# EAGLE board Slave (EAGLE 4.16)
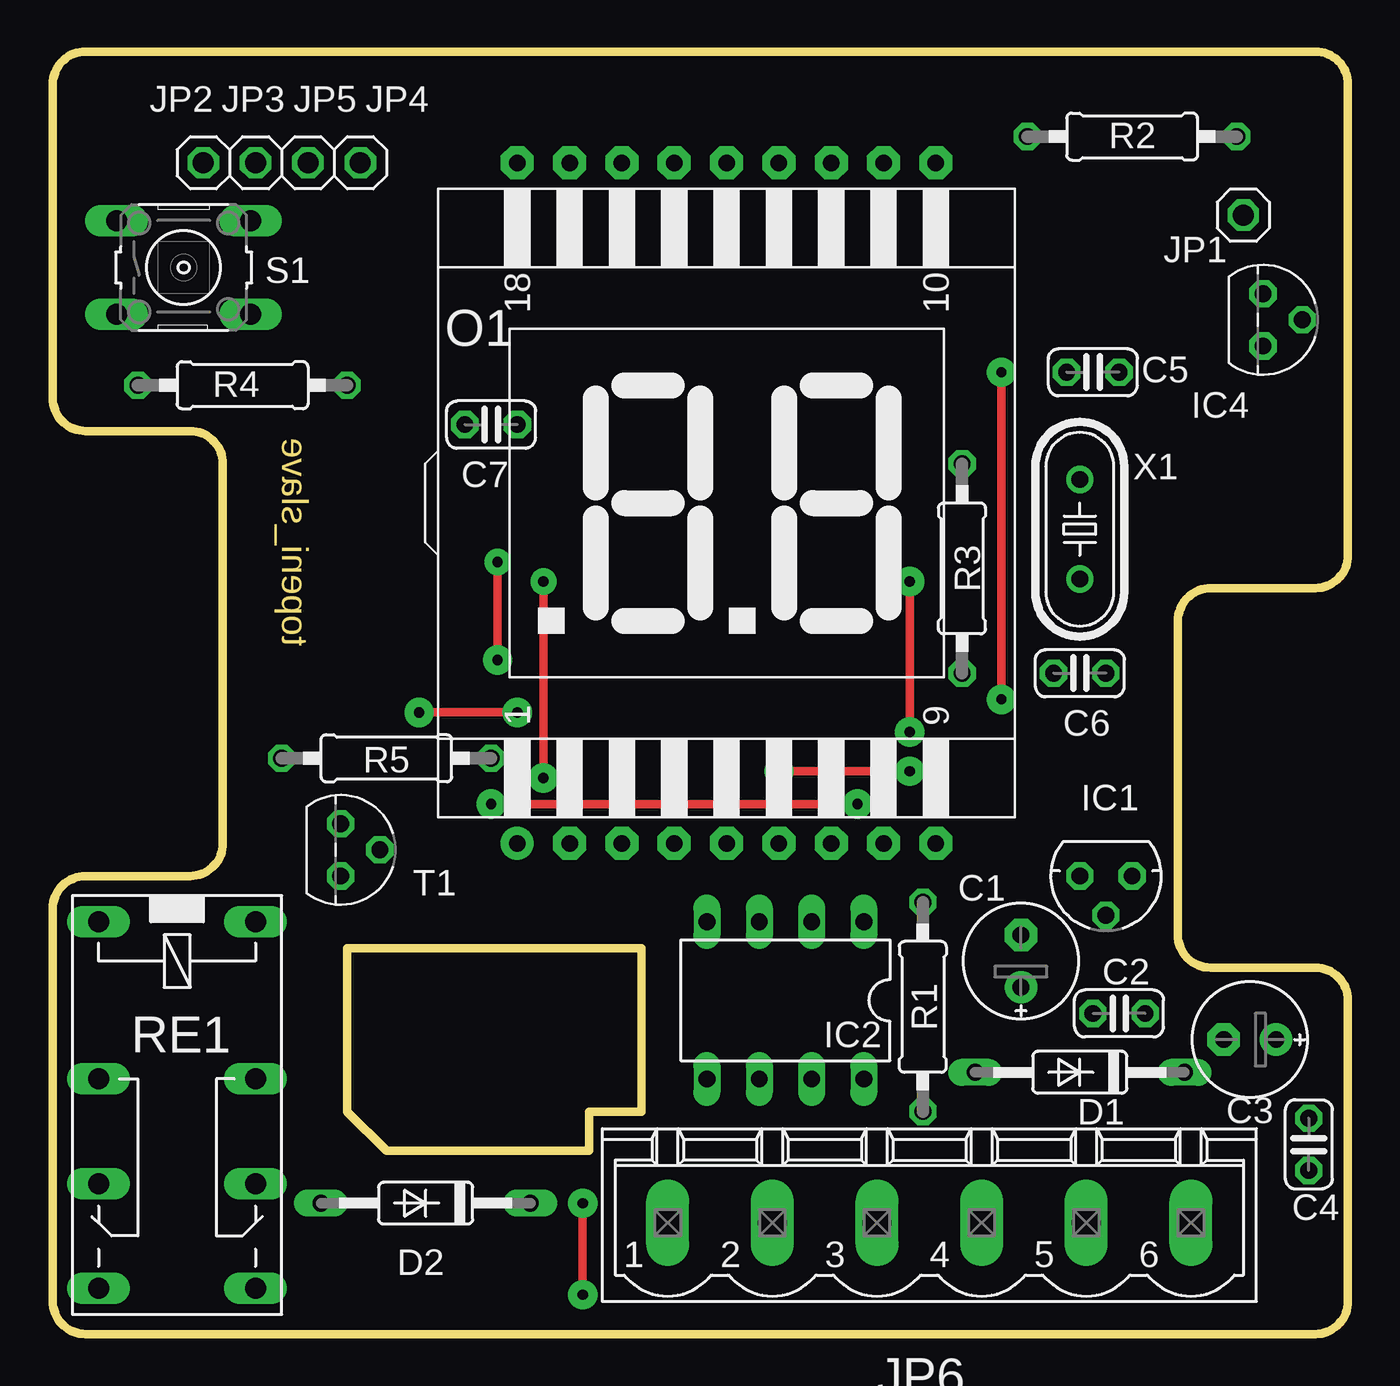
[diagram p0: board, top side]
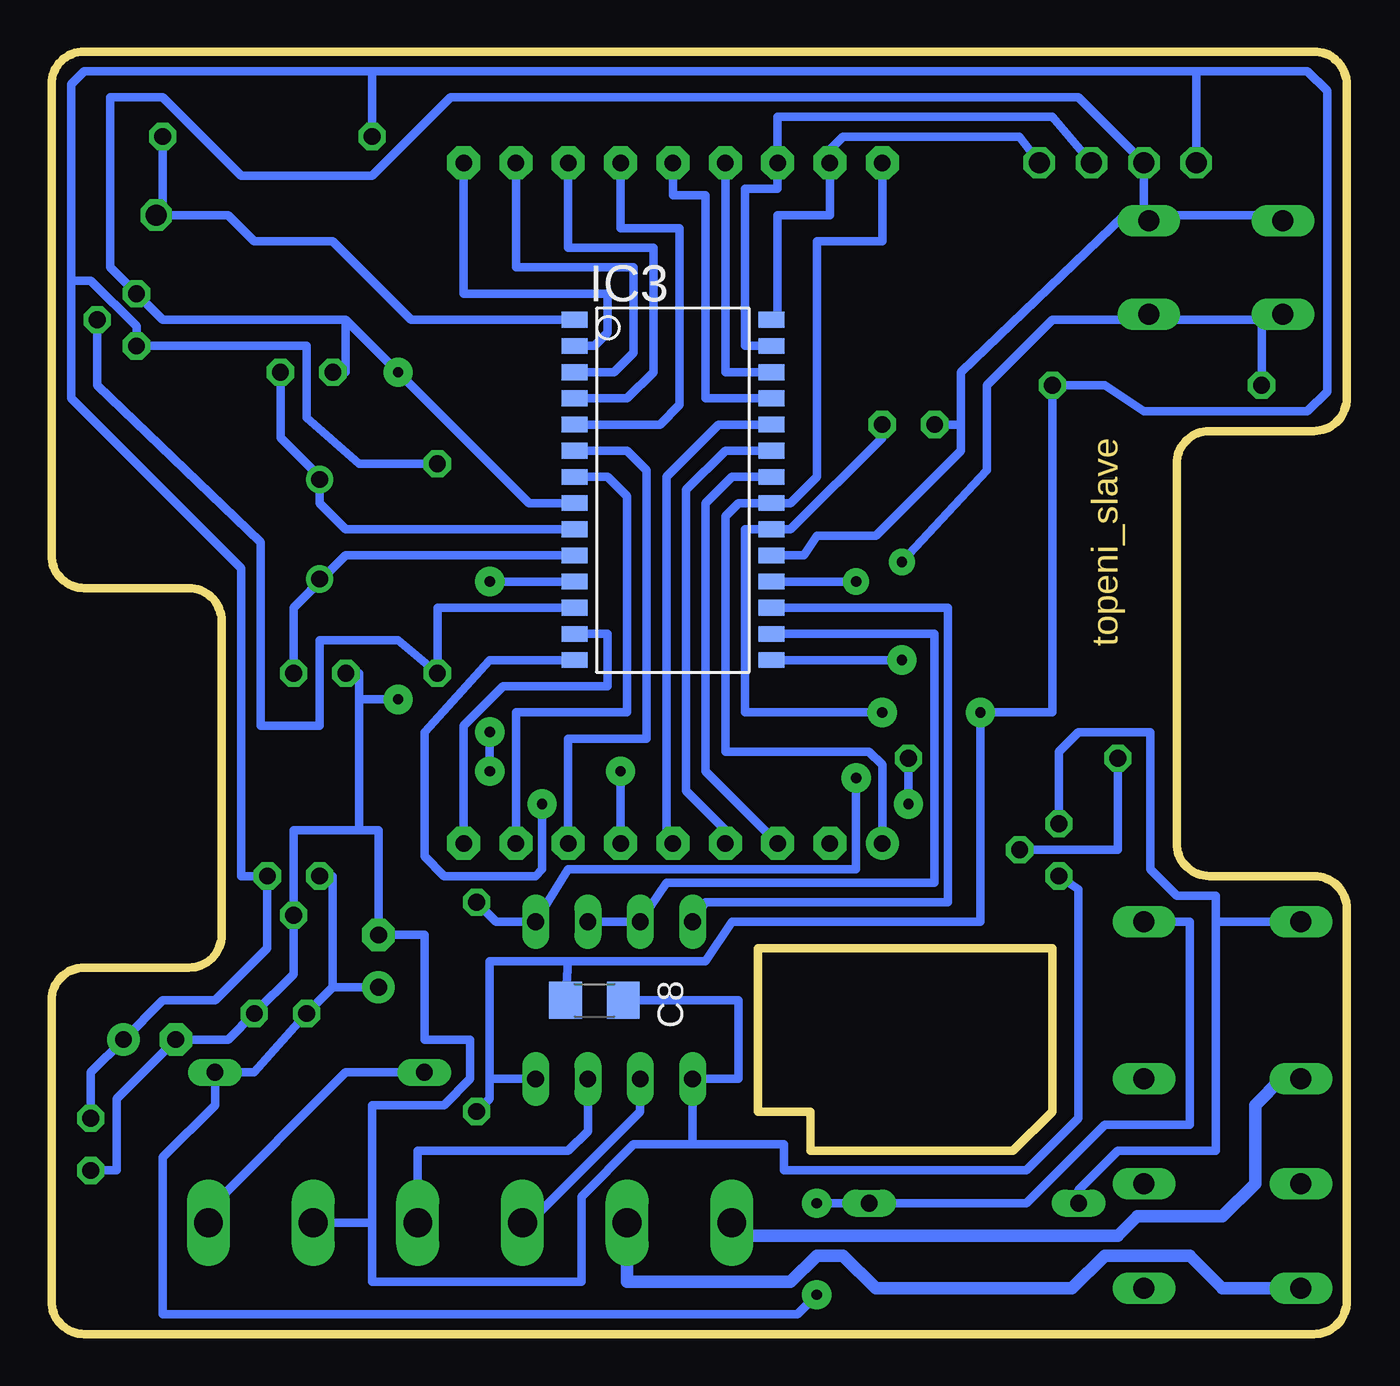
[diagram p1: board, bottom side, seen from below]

Size 62.86 x 62.23 mm. Coordinates in mm from the lower left corner, seen from the top.
Outline: 14.29,12.38 14.29,16.83
Outline: 14.29,16.83 14.29,18.73 28.57,18.73 28.57,10.8 26.03,10.8 26.03,8.89 16.19,8.89 14.29,10.8 14.29,16.83
Outline: 61.28,62.23 1.59,62.23 arc90 0,60.64 0,45.4 arc90 1.59,43.82 6.67,43.82 arc-90 8.25,42.23 8.25,23.81 arc-90 6.67,22.23 1.59,22.23 arc90 0,20.64 0,1.59 arc90 1.59,0 61.28,0 arc90 62.86,1.59 62.86,16.19 arc90 61.28,17.78 56.2,17.78 arc-90 54.61,19.37 54.61,34.61 arc-90 56.2,36.2 61.28,36.2 arc90 62.86,37.78 62.86,60.64 arc90 61.28,62.23
Copper layers (1*16): Top 0.035mm / dielectric 1.5mm / Bottom 0.035mm
Design rules "default": minimum track width 10mil, minimum drill 24mil, track to track 8mil, track to pad 8mil, pad to pad 8mil, via to via 8mil, smd to smd 8mil, copper to edge 40mil, drill to drill 8mil, minimum pad ring 10mil, minimum via ring 8mil, stop-mask expansion 4mil, vias tented up to drill 0mil, thermal gap 10mil

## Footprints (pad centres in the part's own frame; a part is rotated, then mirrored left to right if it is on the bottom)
E2,5-6E = drill 0.813 pad 1.575 round: + -1.27,0 | drill 0.813 pad 1.575 octagon: - 1.27,0
C025-024X044 = drill 0.813 octagon: 1 -1.27,0; 2 1.27,0
C1206 = smd 1.6 x 1.8: 1 -1.4,0; 2 1.4,0
DO35-10 = drill 0.813 long: A 5.08,0; C -5.08,0
78LXX = drill 0.813 octagon: GND 0,1.905; IN 1.27,0; OUT -1.27,0
DIL08 = drill 0.813 long: 1 -3.81,-3.81; 2 -1.27,-3.81; 3 1.27,-3.81; 4 3.81,-3.81; 5 3.81,3.81; 6 1.27,3.81; 7 -1.27,3.81; 8 -3.81,3.81
SO28W = smd 0.762 x 1.27: 1 -7.62,-4.78; 2 -6.35,-4.78; 3 -5.08,-4.78; 4 -3.81,-4.78; 5 -2.54,-4.78; 6 -1.27,-4.78; 7 0,-4.78; 8 1.27,-4.78; 9 2.54,-4.78; 10 3.81,-4.78; 11 5.08,-4.78; 12 6.35,-4.78; 13 7.62,-4.78; 14 8.89,-4.78; 15 8.89,4.78; 16 7.62,4.78; 17 6.35,4.78; 18 5.08,4.78; 19 3.81,4.78; 20 2.54,4.78; 21 1.27,4.78; 22 0,4.78; 23 -1.27,4.78; 24 -2.54,4.78; 25 -3.81,4.78; 26 -5.08,4.78; 27 -6.35,4.78; 28 -7.62,4.78
TO-92 = drill 0.813 octagon: 1 1.27,0; 2 0,1.905; 3 -1.27,0
1X01 = drill 1.016 octagon: 1 0,0
MSTBV6 = drill 1.397 long: 1 -12.7,0; 2 -7.62,0; 3 -2.54,0; 4 2.54,0; 5 7.62,0; 6 12.7,0
SI112 = drill 0.8 pad 1.6 round: 1 -10.16,-16.51 | drill 0.8 pad 1.6 octagon: 2 -7.62,-16.51; 3 -5.08,-16.51; 4 -2.54,-16.51; 5 0,-16.51; 6 2.54,-16.51; 7 5.08,-16.51; 8 7.62,-16.51; 9 10.16,-16.51; 10 10.16,16.51; 11 7.62,16.51; 12 5.08,16.51; 13 2.54,16.51; 14 0,16.51; 15 -2.54,16.51; 16 -5.08,16.51; 17 -7.62,16.51; 18 -10.16,16.51
0207/10 = drill 0.813 octagon: 1 -5.08,0; 2 5.08,0
351 = drill 1.016 long: 1 -3.81,-3.81; 16 -3.81,3.81; O1 8.89,-3.81; O2 8.89,3.81; P1 3.81,-3.81; P2 3.81,3.81; S1 13.97,-3.81; S2 13.97,3.81
B3F-10XX = drill 1.016 long: 1 -3.251,2.261; 2 3.251,2.261; 3 -3.251,-2.261; 4 3.251,-2.261
TO92 = drill 0.813 octagon: 1 1.27,0; 2 0,1.905; 3 -1.27,0
HC49/S = drill 0.813 round: 1 -2.413,0; 2 2.413,0

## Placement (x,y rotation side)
C1  [E2,5-6E]  46.99,18.1 90 top
C2  [C025-024X044]  51.75,15.56 0 top
C3  [E2,5-6E]  58.1,14.29 180 top
C4  [C025-024X044]  60.96,9.21 270 top
C5  [C025-024X044]  50.48,46.67 0 top
C6  [C025-024X044]  49.85,32.07 0 top
C7  [C025-024X044]  21.27,44.13 0 top
C8  [C1206]  36.51,16.19 0 bottom
D1  1N4148  [DO35-10]  49.85,12.7 180 top
D2  1N4148  [DO35-10]  18.1,6.35 180 top
IC1  [78LXX]  51.12,22.23 180 top
IC2  [DIL08]  35.56,16.19 180 top
IC3  PIC16873SO  [SO28W]  32.7,41.59 270 bottom
IC4  TO-92  [TO-92]  58.74,49.21 270 top
JP1  [1X01]  57.78,54.29 0 top
JP2  [1X01]  7.3,56.83 0 top
JP3  [1X01]  9.84,56.83 0 top
JP4  [1X01]  14.92,56.83 0 top
JP5  [1X01]  12.38,56.83 0 top
JP6  MSTBV6  [MSTBV6]  42.54,5.4 0 top
O1  [SI112]  32.7,40.32 0 top
R1  [0207/10]  42.23,15.87 90 top
R2  [0207/10]  52.39,58.1 180 top
R3  [0207/10]  44.13,37.15 90 top
R4  [0207/10]  9.21,46.04 180 top
R5  [0207/10]  16.19,27.94 0 top
RE1  351  [351]  6.03,16.19 270 top
S1  [B3F-10XX]  6.35,51.75 0 top
T1  BC547  [TO92]  13.97,23.5 270 top
U$1  [ARROW<--]  not placed on the board
U$4  [ARROW-->]  not placed on the board
X1  [HC49/S]  49.85,39.05 90 top

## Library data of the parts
C1-C8 R1-R5 = rcl
D1 D2 = diode
IC1 = v-reg
IC2 IC4 = ic-package
IC3 = microchip
JP1-JP5 = pinhead
JP6 = con-phoenix-508
O1 = lcd-7seg
RE1 = relay
S1 = switch-omron
T1 = transistor-npn
U$1 U$4 = marks
X1 = crystal

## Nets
+12V: C1.+ C2.1 D1.C D2.C IC1.IN RE1.16
CLOCK: IC3.27 JP5.1 O1.16
DATA: IC3.28 JP4.1 O1.17
N$1: JP6.2 RE1.S1
N$2: IC3.1 JP1.1 R2.1
N$3: JP6.1 RE1.P1
N$4: IC3.7 O1.8
N$5: C5.2 IC3.9 X1.2
N$6: IC3.26 O1.15
N$7: IC3.11 O1.6
N$8: IC3.25 O1.14
N$9: IC3.24 O1.5
N$11: D2.A RE1.1 T1.3
N$12: R5.1 T1.2
N$13: C6.2 IC3.10 X1.1
N$14: D1.A JP6.6
N$16: IC3.22 O1.3
N$17: IC3.23 O1.4
N$19: IC3.21 O1.1 O1.18
N$21: IC2.2 IC2.3 IC3.16
N$22: IC2.1 IC3.18 R1.2
N$23: IC3.6 O1.7
N$24: IC3.15 R4.2 S1.3 S1.4
N$27: IC3.13 O1.9
N$28: IC3.14 R5.2
N$31: IC3.12 IC4.2 R3.1
N$32: IC3.5 O1.13
N$33: IC3.4 O1.12
N$34: IC3.3 O1.11
N$35: IC3.2 O1.10
N$37: IC2.6 JP6.3
N$38: IC2.7 JP6.4
N$39: IC2.4 IC3.17
VDD: C3.+ C4.1 C7.2 C8.1 IC1.OUT IC2.8 IC3.20 IC4.1 JP2.1 R1.1 R2.2 R3.2 R4.1
VSS: C1.- C2.2 C3.- C4.2 C5.1 C6.1 C7.1 C8.2 IC1.GND IC2.5 IC3.8 IC3.19 IC4.3 JP3.1 JP6.5 S1.1 S1.2 T1.1

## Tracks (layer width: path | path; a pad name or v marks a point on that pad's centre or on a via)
+12V  (via drill 0.5 pad 1.42)
  Top 0.406: v25.72,6.35 v25.72,1.91
  Bottom 0.406: v25.72,1.91 26.67,0.95 57.47,0.95 57.47,8.57 54.93,11.11 D1.C 53.02,12.7 C2.1 49.21,16.83 | v25.72,6.35 D2.C 15.56,6.35 11.75,10.16 7.62,10.16 7.62,20 RE1.16 | 49.21,16.83 C1.+ | IC1.IN 49.21,22.23 49.21,16.83
CLOCK
  Bottom 0.406: JP5.1 14.29,59.06 27.62,59.06 O1.16 27.62,55.56 29.21,55.56 29.21,47.94 IC3.27 27.62,47.94
DATA
  Bottom 0.406: JP4.1 15.87,58.1 24.45,58.1 25.08,57.47 O1.17 25.08,54.29 27.62,54.29 27.62,49.21 IC3.28
N$1
  Bottom 0.61: JP6.2 34.92,2.54 26.99,2.54 25.72,3.81 24.45,3.81 22.86,2.22 13.33,2.22 11.75,3.81 7.62,3.81 6.03,2.22 RE1.S1 1.91,2.22
N$2
  Bottom 0.406: IC3.1 45.4,49.21 49.21,53.02 53.02,53.02 54.29,54.29 JP1.1 57.47,54.61 R2.1
N$3
  Bottom 0.254: 29.53,4.76 JP6.1
  Bottom 0.61: 29.53,5.4 29.53,4.76 11.11,4.76 10.16,5.71 6.03,5.71 4.45,7.3 4.45,11.11 3.18,12.38 RE1.P1
N$4
  Bottom 0.406: O1.8 40.32,30.16 34.92,30.16 34.92,40.64 35.88,41.59 IC3.7 37.78,41.59
N$5
  Bottom 0.406: IC3.9 48.58,39.05 49.85,40.32 X1.2 49.85,41.59 51.75,43.5 C5.2 51.75,46.99
N$6
  Bottom 0.406: 27.62,46.67 IC3.26 30.16,46.67 O1.15
N$7  (via drill 0.5 pad 1.42)
  Top 0.406: v35.24,27.3 v41.59,27.3 | v41.59,29.21 v41.59,36.51
  Bottom 0.406: v41.59,27.3 v41.59,29.21 | O1.6 v35.24,27.3 | v41.59,36.51 IC3.11 37.46,36.51
N$8
  Bottom 0.406: 27.62,45.4 IC3.25 31.12,45.4 31.12,55.24 32.7,55.24 O1.14
N$9
  Bottom 0.406: 27.62,44.13 IC3.24 30.48,44.13 33.02,41.59 33.02,24.13 O1.5
N$11
  Bottom 0.406: T1.3 13.97,28.26 13.02,29.21 9.52,29.21 9.52,22.54 8.25,21.27 6.35,21.27 6.35,20 | D2.A 13.02,6.99 11.11,8.89 6.35,8.89 6.35,20 | 6.35,20 RE1.1
N$12
  Bottom 0.406: R5.1 11.11,23.49 T1.2
N$13
  Bottom 0.406: 50.48,35.88 51.12,35.24 C6.2 | 50.48,35.88 48.58,37.78 IC3.10 37.15,37.78 | 50.48,35.88 X1.1
N$14
  Bottom 0.406: JP6.6 55.24,6.03 48.58,12.7 D1.A
N$16
  Bottom 0.406: 27.62,41.59 IC3.22 29.85,41.59 31.12,40.32 31.12,27.3 O1.3
N$17
  Bottom 0.406: 27.62,42.86 IC3.23 30.16,42.86 32.07,40.96 32.07,26.35 30.16,24.45 O1.4
N$19
  Bottom 0.406: 28.26,40.32 29.53,40.32 30.16,39.69 30.16,28.26 23.18,28.26 22.54,27.62 O1.1 | O1.18 22.54,53.02 25.72,53.02 25.72,41.59 26.99,40.32 27.62,40.32 | 28.26,40.32 IC3.21 27.62,40.32 | 28.26,40.32 27.62,40.32
N$21
  Bottom 0.406: IC2.2 IC2.3 33.02,21.91 20,21.91 20,33.97 IC3.16 28.26,33.97
N$22  (via drill 0.5 pad 1.27, 0.5 pad 1.42)
  Top 0.406: v23.81,26.99 v23.81,36.51
  Bottom 0.406: 28.26,36.51 IC3.18 v23.81,36.51 | v23.81,26.99 23.81,22.54 37.78,22.54 IC2.1 41.28,20 R1.2
N$23
  Bottom 0.406: O1.7 37.78,28.89 33.97,28.89 33.97,41.91 34.92,42.86 IC3.6 37.78,42.86
N$24  (via drill 0.5 pad 1.27, 0.5 pad 1.42)
  Top 0.406: v21.59,37.46 v21.59,32.7
  Bottom 0.406: R4.2 4.13,49.21 | 4.13,49.21 10.48,49.21 | 10.48,49.21 14.29,49.21 17.46,46.04 17.46,41.91 v21.59,37.46 | v21.59,32.7 IC3.15 28.26,32.7 | 4.13,49.21 S1.3 | 10.48,49.21 S1.4
N$27
  Bottom 0.406: O1.9 42.86,29.53 40.96,31.43 35.88,31.43 35.88,33.97 IC3.13 37.78,33.97
N$28  (via drill 0.5 pad 1.42)
  Top 0.406: v21.27,25.72 v39.05,25.72
  Bottom 0.406: v21.27,25.72 R5.2 | 37.15,32.7 IC3.14 41.59,32.7 44.77,29.21 44.77,23.18 43.82,22.23 39.37,22.23 39.05,22.54 v39.05,25.72
N$31
  Bottom 0.406: 37.15,35.24 IC3.12 44.13,35.24 R3.1 46.04,33.65 49.85,33.65 49.85,29.53 52.71,29.53 52.71,38.42 60.64,46.04 IC4.2
N$32
  Bottom 0.406: O1.13 35.24,53.66 32.39,53.66 32.39,45.09 33.34,44.13 IC3.5 37.78,44.13
N$33
  Bottom 0.406: O1.12 37.78,52.71 33.65,52.71 33.65,46.67 34.92,45.4 IC3.4 37.78,45.4
N$34
  Bottom 0.406: O1.11 40.32,51.75 34.61,51.75 34.61,47.63 35.56,46.67 IC3.3 37.78,46.67
N$35
  Bottom 0.406: O1.10 42.86,50.48 35.88,50.48 35.88,48.58 36.51,47.94 IC3.2 37.78,47.94
N$37
  Bottom 0.254: JP6.3 39.05,6.03
  Bottom 0.406: IC2.6 34.29,10.8 39.05,6.03 40,5.08
N$38
  Bottom 0.406: 36.83,12.7 IC2.7 36.83,9.84 37.78,8.89 45.09,8.89 JP6.4
N$39
  Bottom 0.406: IC3.17 19.37,35.24 19.37,20.96 31.12,20.96 IC2.4
VDD  (via drill 0.5 pad 1.42)
  Top 0.406: v17.78,30.16 v22.54,30.16
  Bottom 0.406: 61.91,51.12 61.91,60.64 61.28,61.28 47.31,61.28 | 61.91,51.12 61.91,45.4 53.66,37.15 53.66,22.23 IC1.OUT 52.39,18.73 54.93,16.19 57.47,16.19 C3.+ 60.96,12.7 C4.1 | 47.31,61.28 R2.2 | 7.3,61.28 1.91,61.28 0.95,60.32 0.95,45.72 1.91,44.77 9.84,44.77 11.75,46.04 R4.1 14.29,30.16 v17.78,30.16 17.78,20 29.85,20 31.12,18.1 37.78,18.1 | 7.3,61.28 47.31,61.28 | 27.62,39.05 IC3.20 27.94,39.05 | 27.94,39.05 26.99,39.05 22.54,43.5 C7.2 | 41.59,12.38 41.59,18.1 37.78,18.1 | 27.94,39.05 29.21,39.05 29.21,30.16 v22.54,30.16 | 61.91,51.12 60.96,51.12 58.74,48.89 IC4.1 50.48,47.94 50.48,44.45 47.94,42.23 R3.2 | 7.3,61.28 JP2.1 | R1.1 41.59,11.43 41.59,12.38 | 41.59,12.38 IC2.8 | 37.78,18.1 C8.1
VSS  (via drill 0.5 pad 1.42)
  Top 0.406: v46.04,30.8 v46.04,46.67
  Bottom 0.406: 28.26,37.78 IC3.19 26.35,37.78 25.72,38.74 22.86,38.74 18.73,42.86 18.73,44.13 | 18.73,44.13 C7.1 | 18.73,44.13 18.73,46.67 10.8,54.29 | S1.1 3.49,54.29 9.52,54.29 | 9.52,54.29 S1.2 | 10.8,54.29 9.52,54.29 | 9.84,54.29 10.8,54.29 | 9.84,54.29 9.52,54.29 | 9.84,54.29 JP3.1 13.02,60.01 43.5,60.01 47.31,56.2 53.66,56.2 57.47,60.01 60.01,60.01 60.01,51.75 IC4.3 57.47,49.21 48.58,49.21 | C4.2 59.69,7.94 59.69,11.43 C3.- 54.29,14.29 C2.2 51.12,17.46 IC1.GND 51.12,24.45 47.94,24.45 | C5.1 48.58,46.67 48.58,49.21 | 37.15,40.32 IC3.8 39.69,40.32 v46.04,46.67 48.58,49.21 | C6.1 47.94,32.07 47.94,30.8 | 47.94,30.8 v46.04,30.8 | 47.94,24.45 47.94,30.8 | 47.94,24.45 46.99,24.45 C1.- 44.77,19.37 44.77,14.29 42.54,14.29 42.54,12.38 43.82,11.11 47.31,11.11 47.31,5.4 | 47.31,5.4 JP6.5 | 47.31,5.4 47.31,2.54 37.15,2.54 37.15,6.67 34.61,9.21 31.75,9.21 | 35.24,16.19 C8.2 29.53,16.19 29.53,12.38 IC2.5 31.75,9.21 | 31.75,9.21 27.3,9.21 27.3,7.94 15.56,7.94 13.02,10.48 13.02,21.59 T1.1

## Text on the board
Dimension: topeni_slave
Measures: 63 mm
